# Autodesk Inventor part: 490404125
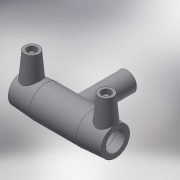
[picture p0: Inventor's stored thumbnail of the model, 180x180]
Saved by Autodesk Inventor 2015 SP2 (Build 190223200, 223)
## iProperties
Created: 2017-06
Part Number: 490404125
Material: Generic
Description: PLASSON TEE 125-125-125
Document SubType Name: Modeling
Designer: KIM
Mass: 57.3761 g
Surface Area: 241.06 cm^2
Volume: 57.3761 cm^3
Density: 1 g/cm^3
Appearance: Default
Author: KIM
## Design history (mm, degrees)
derived "490404.ipt"
feature "Solid1::490404.ipt"
tag "TaggingFeature1"
body "Solid1"
other parameters: "d0" = 382, "d1" = 125, "d2" = 165, "d3" = 86, "d4" = 95.5, "d5" = 148.5, "d6" = 118.75, "d7" = 125, "d8" = 168 deg, "d10" = 34.4, "d11" = 11.46667, "d13" = 382, "d14" = 17.6296, "d17" = 112.5, "d18" = 125, "d19" = 3.52592, "d20" = 168 deg, "d22" = 153.45, "d23" = 165, "d24" = 148.8465, "d25" = 135 deg, "d26" = 267.4, "d27" = 135 deg, "d29" = 88, "d30" = 15, "d31" = 152.8, "d34" = 5 deg, "d35" = 15, "d39" = 5 deg, "d40" = 9.6, "d41" = 4.8, "d42" = 6, "d43" = 0, "d45" = 4, "d46" = 14, "d47" = 0, "d48" = -177, "d49" = 125, "d51" = 0, "d54" = 0, "d55" = 148.5, "d56" = 165, "d57" = 133.7, "d58" = 135 deg, "d59" = 86, "d60" = 86, "d61" = 135 deg, "d62" = 177, "d72" = 173.81, "d73" = 86.905, "d74" = -177, "d75" = 131.25, "d77" = 0, "d80" = 0, "d81" = 125, "d82" = 94.5, "d83" = 0, "d84" = 3, "d85" = 0, "d86" = 3, "d87" = 0, "d88" = 24.94, "d89" = 6.235, "d90" = 24.94, "d_" = 125, "L_" = 382, "L_1" = 86, "D_" = 165, "A_" = 88, "d_2" = 12, "H_" = 177
